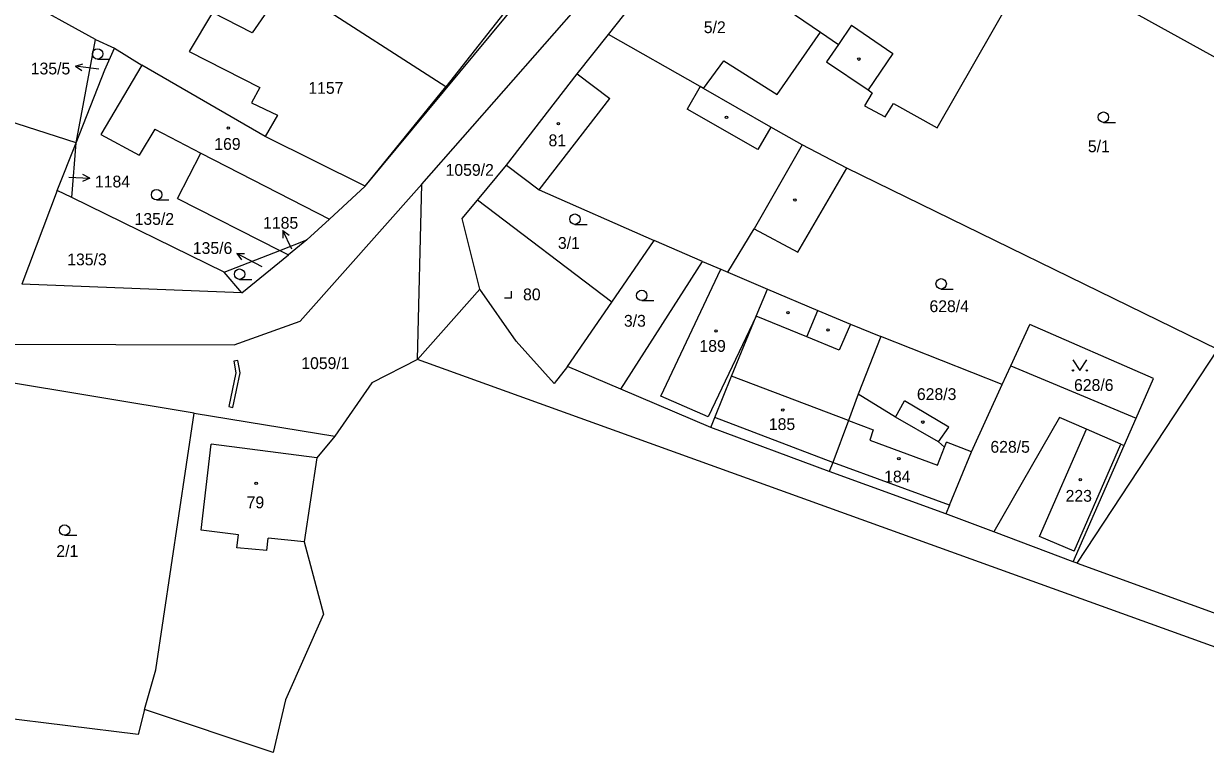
# Model space of a CAD drawing. Extents: x -694609 to -690140, y -1033292 to -1029794.
# Drawn here: x -692609.2 to -692438.9, y -1031915.8 to -1031810 of the extents above; entities that cross this region are included whole.
import ezdxf
from ezdxf.enums import TextEntityAlignment as Align

# ---------------------------------------------------------------- set-up
doc = ezdxf.new("R2010")
doc.units = 0
doc.header["$LTSCALE"] = 0.68
for name, color, linetype, lineweight in [('1', 7, 'Continuous', 25), ('13', 7, 'Continuous', 13), ('3', 7, 'Continuous', 25), ('4', 7, 'Continuous', 13), ('5', 7, 'Continuous', 25), ('7', 7, 'Continuous', 13)]:
    doc.layers.add(name, color=color, linetype=linetype, lineweight=lineweight)
doc.layers.add('2', color=7, linetype='Continuous')

msp = doc.modelspace()

# ---------------------------------------------------------------- linework, layer by layer
at = {"layer": '1'}
for p, q in [((-692559.98, -1031833.38), (-692491.21, -1031750.69)), ((-692551.82, -1031833.09), (-692492.12, -1031765.22)), ((-692524.91, -1031811.52), (-692514, -1031797.79)), ((-692514, -1031797.79), (-692494.36, -1031811.2)), ((-692598.83, -1031812.27), (-692622.58, -1031799.12)), ((-692477.55, -1031824.98), (-692463.48, -1031800.46)), ((-692463.48, -1031800.46), (-692416.83, -1031826.23)), ((-692535.46, -1031802.7), (-692548.33, -1031819.07)), ((-692548.33, -1031819.07), (-692571.38, -1031804.26)), ((-692581.95, -1031808.36), (-692585.34, -1031814)), ((-692529.44, -1031817.23), (-692524.91, -1031811.52)), ((-692511.71, -1031819.01), (-692524.91, -1031811.52)), ((-692500.6, -1031820.18), (-692494.36, -1031811.2)), ((-692494.36, -1031811.2), (-692491.77, -1031812.97)), ((-692601.62, -1031827.16), (-692598.83, -1031812.27)), ((-692598.83, -1031812.27), (-692596.09, -1031813.52)), ((-692597.46, -1031816.65), (-692596.09, -1031813.52)), ((-692596.09, -1031813.52), (-692592.13, -1031815.98)), ((-692491.77, -1031812.97), (-692493.47, -1031815.48)), ((-692585.34, -1031814), (-692575.15, -1031819.19)), ((-692511.22, -1031819.3), (-692508.29, -1031815.33)), ((-692508.29, -1031815.33), (-692500.6, -1031820.18)), ((-692601.62, -1031827.16), (-692597.46, -1031816.65)), ((-692592.13, -1031815.98), (-692598.07, -1031825.96)), ((-692574.38, -1031826.23), (-692592.13, -1031815.98)), ((-692493.47, -1031815.48), (-692487.48, -1031819.53)), ((-692539.58, -1031830.38), (-692529.44, -1031817.23)), ((-692575.15, -1031819.19), (-692576.36, -1031821.38)), ((-692559.98, -1031833.38), (-692548.33, -1031819.07)), ((-692511.22, -1031819.3), (-692511.71, -1031819.01)), ((-692501.51, -1031824.9), (-692511.22, -1031819.3)), ((-692486.9, -1031819.93), (-692488.02, -1031821.84)), ((-692487.48, -1031819.53), (-692486.9, -1031819.93)), ((-692601.62, -1031827.16), (-692620.85, -1031820.99)), ((-692576.36, -1031821.38), (-692572.61, -1031823.17)), ((-692488.02, -1031821.84), (-692485.02, -1031823.41)), ((-692485.02, -1031823.41), (-692483.84, -1031821.47)), ((-692483.84, -1031821.47), (-692477.55, -1031824.98)), ((-692572.61, -1031823.17), (-692574.38, -1031826.23)), ((-692590.27, -1031825.16), (-692592.55, -1031828.91)), ((-692590.27, -1031825.16), (-692583.63, -1031828.62)), ((-692496.98, -1031827.43), (-692501.51, -1031824.9)), ((-692604.33, -1031833.99), (-692601.62, -1031827.16)), ((-692602.24, -1031835.01), (-692601.62, -1031827.16)), ((-692598.07, -1031825.96), (-692592.55, -1031828.91)), ((-692559.98, -1031833.38), (-692574.38, -1031826.23)), ((-692587, -1031835.14), (-692583.63, -1031828.62)), ((-692490.54, -1031830.78), (-692496.98, -1031827.43)), ((-692543.77, -1031835.39), (-692539.58, -1031830.38)), ((-692539.58, -1031830.38), (-692534.89, -1031833.91)), ((-692497.6, -1031842.9), (-692490.54, -1031830.78)), ((-692437.1, -1031856.91), (-692490.54, -1031830.78)), ((-692604.33, -1031833.99), (-692609.44, -1031847.52)), ((-692602.24, -1031835.01), (-692604.33, -1031833.99)), ((-692569.33, -1031852.85), (-692551.82, -1031833.09)), ((-692565.12, -1031838.16), (-692559.98, -1031833.38)), ((-692552.44, -1031858.36), (-692551.82, -1031833.09)), ((-692534.89, -1031833.91), (-692518.33, -1031841.21)), ((-692580.29, -1031845.76), (-692602.24, -1031835.01)), ((-692587, -1031835.14), (-692572.26, -1031842.63)), ((-692546.01, -1031838.05), (-692543.77, -1031835.39)), ((-692524.42, -1031850.07), (-692543.77, -1031835.39)), ((-692568.36, -1031841.11), (-692565.12, -1031838.16)), ((-692543.42, -1031848.23), (-692546.01, -1031838.05)), ((-692507.69, -1031845.79), (-692503.89, -1031839.51)), ((-692503.89, -1031839.51), (-692497.6, -1031842.9)), ((-692580.29, -1031845.76), (-692572.26, -1031842.63)), ((-692572.26, -1031842.63), (-692568.36, -1031841.11)), ((-692572.26, -1031842.63), (-692571.01, -1031843.27)), ((-692568.36, -1031841.11), (-692571.01, -1031843.27)), ((-692524.42, -1031850.07), (-692518.33, -1031841.21)), ((-692511.34, -1031844.22), (-692518.33, -1031841.21)), ((-692577.72, -1031848.74), (-692571.01, -1031843.27)), ((-692523.13, -1031862.63), (-692511.34, -1031844.22)), ((-692511.34, -1031844.22), (-692508.72, -1031845.35)), ((-692577.72, -1031848.74), (-692580.29, -1031845.76)), ((-692508.72, -1031845.35), (-692507.69, -1031845.79)), ((-692507.69, -1031845.79), (-692502.01, -1031848.24)), ((-692577.72, -1031848.74), (-692609.44, -1031847.52)), ((-692543.42, -1031848.23), (-692552.44, -1031858.36)), ((-692538.23, -1031855.72), (-692543.42, -1031848.23)), ((-692503.62, -1031852.09), (-692502.01, -1031848.24)), ((-692530.81, -1031859.38), (-692524.42, -1031850.07)), ((-692578.86, -1031856.24), (-692569.33, -1031852.85)), ((-692507.19, -1031860.76), (-692503.62, -1031852.09)), ((-692490.01, -1031853.24), (-692485.65, -1031855.05)), ((-692466.94, -1031859.28), (-692464.2, -1031853.29)), ((-692446.38, -1031861.1), (-692464.2, -1031853.29)), ((-692615.73, -1031856.13), (-692578.86, -1031856.24)), ((-692532.75, -1031861.81), (-692538.23, -1031855.72)), ((-692485.65, -1031855.05), (-692488.95, -1031863.34)), ((-692468.17, -1031861.97), (-692485.65, -1031855.05)), ((-692457.39, -1031887.7), (-692437.1, -1031856.91)), ((-692584.6, -1031866.07), (-692624.83, -1031859.42)), ((-692552.44, -1031858.36), (-692558.99, -1031861.69)), ((-692392.4, -1031916.03), (-692552.44, -1031858.36)), ((-692530.81, -1031859.38), (-692532.75, -1031861.81)), ((-692523.13, -1031862.63), (-692530.81, -1031859.38)), ((-692468.17, -1031861.97), (-692466.94, -1031859.28)), ((-692466.94, -1031859.28), (-692448.89, -1031866.81)), ((-692509.58, -1031866.7), (-692507.19, -1031860.76)), ((-692448.89, -1031866.81), (-692446.38, -1031861.1)), ((-692558.99, -1031861.69), (-692564.35, -1031869.39)), ((-692510.14, -1031868.12), (-692523.13, -1031862.63)), ((-692472.61, -1031871.64), (-692468.17, -1031861.97)), ((-692483.57, -1031866.63), (-692488.95, -1031863.34)), ((-692483.57, -1031866.63), (-692482.24, -1031864.3)), ((-692475.88, -1031868.07), (-692482.24, -1031864.3)), ((-692590.15, -1031903.02), (-692584.6, -1031866.07)), ((-692584.6, -1031866.07), (-692564.35, -1031869.39)), ((-692510.14, -1031868.12), (-692509.58, -1031866.7)), ((-692493.11, -1031874.47), (-692510.14, -1031868.12)), ((-692477.35, -1031870.2), (-692475.88, -1031868.07)), ((-692459.91, -1031866.68), (-692469.36, -1031883.19)), ((-692456.03, -1031868.37), (-692459.91, -1031866.68)), ((-692450.61, -1031870.74), (-692448.89, -1031866.81)), ((-692564.35, -1031869.39), (-692566.95, -1031872.5)), ((-692451.06, -1031870.54), (-692456.03, -1031868.37)), ((-692477.35, -1031870.2), (-692476.47, -1031870.97)), ((-692476.47, -1031870.97), (-692476.18, -1031870.24)), ((-692472.61, -1031871.64), (-692476.18, -1031870.24)), ((-692457.97, -1031887.48), (-692450.61, -1031870.74)), ((-692451.06, -1031870.54), (-692450.61, -1031870.74)), ((-692566.95, -1031872.5), (-692568.76, -1031884.61)), ((-692492.6, -1031873.16), (-692493.11, -1031874.47)), ((-692475.76, -1031879.31), (-692472.61, -1031871.64)), ((-692476.28, -1031880.59), (-692493.11, -1031874.47)), ((-692475.76, -1031879.31), (-692476.28, -1031880.59)), ((-692469.36, -1031883.19), (-692476.28, -1031880.59)), ((-692457.97, -1031887.48), (-692469.36, -1031883.19)), ((-692568.76, -1031884.61), (-692565.98, -1031895.02)), ((-692457.39, -1031887.7), (-692457.97, -1031887.48)), ((-692457.39, -1031887.7), (-692435.67, -1031895.57)), ((-692565.98, -1031895.02), (-692571.44, -1031907.34)), ((-692591.78, -1031908.76), (-692590.15, -1031903.02)), ((-692571.44, -1031907.34), (-692573.24, -1031914.94)), ((-692592.68, -1031912.36), (-692623.83, -1031908.5)), ((-692591.78, -1031908.76), (-692592.68, -1031912.36)), ((-692573.24, -1031914.94), (-692591.78, -1031908.76))]:
    msp.add_line(p, q, dxfattribs=at)
for points in [[(-692571.38, -1031804.26), (-692576.24, -1031811.29), (-692581.95, -1031808.36)], [(-692502.01, -1031848.24), (-692494.72, -1031851.28), (-692490.01, -1031853.24)], [(-692488.95, -1031863.34), (-692490.32, -1031867.14), (-692492.6, -1031873.16)]]:
    msp.add_lwpolyline(points, dxfattribs=at)
at = {"layer": '13'}
msp.add_lwpolyline([(-692579.61, -1031865.12), (-692579.02, -1031865.25), (-692577.97, -1031860.26), (-692578.32, -1031858.47), (-692578.91, -1031858.58), (-692578.59, -1031860.26)], close=True, dxfattribs=at)
at = {"layer": '3'}
for p, q in [((-692598.513, -1031815.09), (-692596.763, -1031815.09)), ((-692453.593, -1031824.2), (-692451.843, -1031824.2)), ((-692590.013, -1031835.36), (-692588.263, -1031835.36)), ((-692529.743, -1031838.89), (-692527.993, -1031838.89)), ((-692578.053, -1031846.81), (-692576.303, -1031846.81)), ((-692476.973, -1031848.2), (-692475.223, -1031848.2)), ((-692520.113, -1031849.87), (-692518.363, -1031849.87)), ((-692603.273, -1031883.66), (-692601.523, -1031883.66))]:
    msp.add_line(p, q, dxfattribs=at)
for points in [[(-692539.891, -1031849.49), (-692538.89, -1031849.49), (-692538.89, -1031848.49)], [(-692457.98, -1031858.419), (-692456.98, -1031859.92), (-692455.98, -1031858.419)]]:
    msp.add_lwpolyline(points, dxfattribs=at)
for centre, radius in [((-692598.5129, -1031814.3398), 0.75), ((-692453.5929, -1031823.4498), 0.75), ((-692590.0129, -1031834.6098), 0.75), ((-692529.7429, -1031838.1398), 0.75), ((-692578.0529, -1031846.0598), 0.75), ((-692476.9729, -1031847.4498), 0.75), ((-692520.1129, -1031849.1198), 0.75), ((-692457.98, -1031859.9195), 0.1), ((-692455.98, -1031859.9195), 0.1), ((-692603.2729, -1031882.9098), 0.75)]:
    msp.add_circle(centre, radius, dxfattribs=at)
at = {"layer": '4'}
for p, q in [((-692489.91, -1031810.22), (-692491.77, -1031812.97)), ((-692489.91, -1031810.22), (-692483.92, -1031814.28)), ((-692483.92, -1031814.28), (-692487.48, -1031819.53)), ((-692529.44, -1031817.23), (-692524.73, -1031820.76)), ((-692511.71, -1031819.01), (-692513.59, -1031822.29)), ((-692534.89, -1031833.91), (-692524.73, -1031820.76)), ((-692503.39, -1031828.12), (-692513.59, -1031822.29)), ((-692501.51, -1031824.9), (-692503.39, -1031828.12)), ((-692583.63, -1031828.62), (-692565.12, -1031838.16)), ((-692496.98, -1031827.43), (-692503.89, -1031839.51)), ((-692496.31, -1031855.09), (-692494.72, -1031851.28)), ((-692490.32, -1031867.14), (-692507.19, -1031860.76)), ((-692492.6, -1031873.16), (-692509.58, -1031866.7)), ((-692490.32, -1031867.14), (-692486.78, -1031868.48)), ((-692477.35, -1031870.2), (-692483.57, -1031866.63)), ((-692486.78, -1031868.48), (-692487.26, -1031869.97)), ((-692462.79, -1031883.82), (-692456.03, -1031868.37)), ((-692566.95, -1031872.5), (-692582.16, -1031870.55)), ((-692487.26, -1031869.97), (-692477.49, -1031873.56)), ((-692477.49, -1031873.56), (-692476.47, -1031870.97)), ((-692457.8, -1031885.94), (-692451.06, -1031870.54)), ((-692475.76, -1031879.31), (-692492.6, -1031873.16)), ((-692574.15, -1031885.85), (-692573.95, -1031884.07)), ((-692568.76, -1031884.61), (-692573.95, -1031884.07)), ((-692457.8, -1031885.94), (-692462.79, -1031883.82))]:
    msp.add_line(p, q, dxfattribs=at)
for points in [[(-692503.62, -1031852.09), (-692510.53, -1031866.6), (-692517.38, -1031863.64), (-692508.72, -1031845.35)], [(-692490.01, -1031853.24), (-692491.67, -1031856.99), (-692496.31, -1031855.09), (-692503.62, -1031852.09)], [(-692574.15, -1031885.85), (-692578.47, -1031885.49), (-692578.23, -1031883.59), (-692583.61, -1031882.91), (-692582.16, -1031870.55)]]:
    msp.add_lwpolyline(points, dxfattribs=at)
at = {"layer": '5'}
for centre in [(-692488.8268, -1031815.0892), (-692507.8968, -1031823.4792), (-692579.6968, -1031825.0192), (-692532.1168, -1031824.3892), (-692498.0468, -1031835.3792), (-692499.0468, -1031851.5892), (-692509.4068, -1031854.2392), (-692493.2668, -1031854.0992), (-692499.7868, -1031865.6292), (-692479.6068, -1031867.3692), (-692483.0668, -1031872.6392), (-692575.6668, -1031876.1792), (-692456.9168, -1031875.6492)]:
    msp.add_circle(centre, 0.175, dxfattribs=at)
at = {"layer": '7'}
for p, q in [((-692601.719, -1031816.124), (-692600.786, -1031816.743)), ((-692599.653, -1031832.257), (-692600.627, -1031831.705)), ((-692571.826, -1031839.773), (-692571.837, -1031840.892)), ((-692578.45, -1031843.071), (-692577.801, -1031843.983))]:
    msp.add_line(p, q, dxfattribs=at)
for points in [[(-692598.35, -1031816.54), (-692598.74, -1031816.49), (-692601.719, -1031816.124), (-692600.664, -1031815.749)], [(-692602.65, -1031832.1), (-692599.653, -1031832.257), (-692600.679, -1031832.705)], [(-692570.51, -1031842.47), (-692571.826, -1031839.773), (-692570.936, -1031840.453)], [(-692574.82, -1031845), (-692575.8, -1031844.48), (-692578.45, -1031843.071), (-692577.33, -1031843.099)]]:
    msp.add_lwpolyline(points, dxfattribs=at)

# ---------------------------------------------------------------- texts
at = {"layer": '2'}
for s, p in [('5/2', (-692509.59, -1031811.345)), ('1157', (-692565.62, -1031820.085)), ('169', (-692579.809, -1031828.155)), ('81', (-692532.279, -1031827.635)), ('5/1', (-692454.25, -1031828.495)), ('1059/2', (-692544.9, -1031831.895)), ('135/2', (-692590.34, -1031838.955)), ('1185', (-692572.14, -1031839.515)), ('3/1', (-692530.61, -1031842.415)), ('135/3', (-692600.05, -1031844.785)), ('80', (-692535.949, -1031849.825)), ('628/4', (-692475.81, -1031851.525)), ('3/3', (-692521.1, -1031853.625)), ('189', (-692509.899, -1031857.245)), ('1059/1', (-692565.69, -1031859.725)), ('628/6', (-692454.98, -1031862.875)), ('628/3', (-692477.62, -1031864.185)), ('185', (-692499.899, -1031868.505)), ('628/5', (-692467.03, -1031871.775)), ('184', (-692483.289, -1031876.055)), ('79', (-692575.779, -1031879.775)), ('223', (-692457.139, -1031878.835)), ('2/1', (-692602.88, -1031886.785))]:
    msp.add_text(s, height=1.7, dxfattribs=at).set_placement(p, align=Align.CENTER)
for s, p in [('135/5', (-692602.46, -1031817.292)), ('135/6', (-692579.11, -1031843.145))]:
    msp.add_text(s, height=1.7, dxfattribs=at).set_placement(p, align=Align.RIGHT)
msp.add_text('1184', height=1.7, dxfattribs=at).set_placement((-692598.9, -1031833.572))

doc.saveas('drawing.dxf')
